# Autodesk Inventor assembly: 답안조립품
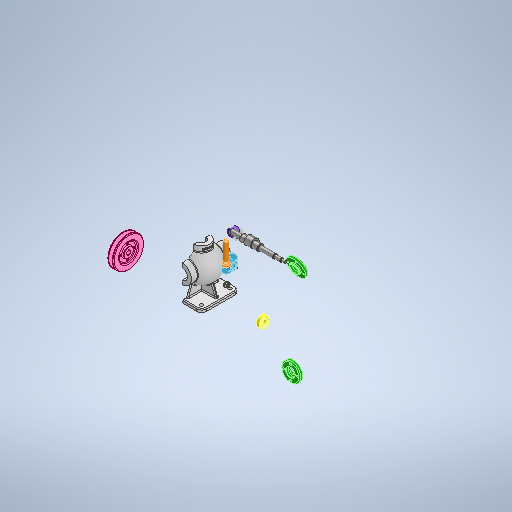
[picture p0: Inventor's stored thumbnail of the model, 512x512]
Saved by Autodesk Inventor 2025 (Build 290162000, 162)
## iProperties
Created: 2024-07
Part Number: 답안조립품
Document SubType Name: Assembly
Designer: anfro
Author: anfro
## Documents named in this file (15)
- D:\Desktop\740708V1011\답안조립품.iam
- D:\Desktop\740708V1011\V-벨트풀리\V-벨트풀리.ipt
- D:\Desktop\740708V1011\너트 M8\너트 M8.ipt
- D:\Desktop\740708V1011\뒤커버\뒤커버.ipt
- D:\Desktop\740708V1011\베어링- 6202\베어링- 6202.ipt
- D:\Desktop\740708V1011\본체.ipt
- D:\Desktop\740708V1011\볼트 M4 x 12\볼트 M4 x 12.ipt
- D:\Desktop\740708V1011\볼트 M4 x 16\볼트 M4 x 16.ipt
- D:\Desktop\740708V1011\상부커버\상부커버.ipt
- D:\Desktop\740708V1011\슬라이드\슬라이드.ipt
- D:\Desktop\740708V1011\앞커버\앞커버.ipt
- D:\Desktop\740708V1011\오일실 15 30 7\오일실 15 30 7.ipt
- D:\Desktop\740708V1011\칼라\칼라.ipt
- D:\Desktop\740708V1011\키 4 x 4 x 12\키 4 x 4 x 12.ipt
- D:\Desktop\740708V1011\편심축\편심축.ipt
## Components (1 placed, 1 different names)
1. V-벨트풀리:1
